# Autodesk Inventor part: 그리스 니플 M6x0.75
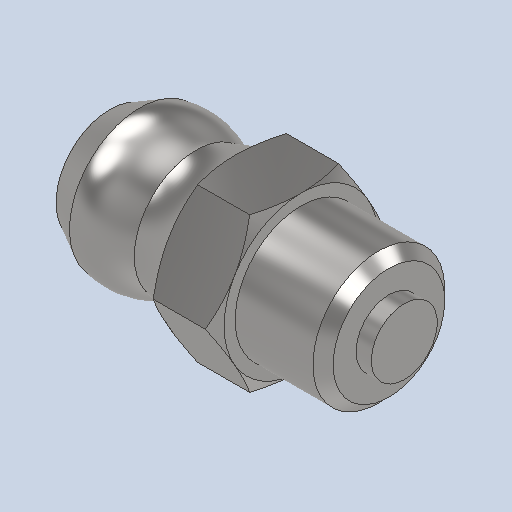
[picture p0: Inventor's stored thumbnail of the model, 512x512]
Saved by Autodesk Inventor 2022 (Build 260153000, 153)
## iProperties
Created: 2024-11
Part Number: 그리스 니플 M6x0.75
Material: 강철, 연강
Description: 윤활 니플, 원추 유형 A
Document SubType Name: Modeling
Designer: PC-12
Density: 7.85 g/cm^3
Appearance: 기본값
Author: jhkim
Sending System: Autodesk Inventor 2025
Preprocessor: ST-DEVELOPER v20
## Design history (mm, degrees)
node "그리스 니플 M6x0.751"
node "솔리드1"
body "Solid1"
